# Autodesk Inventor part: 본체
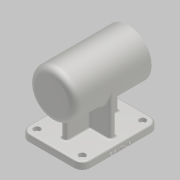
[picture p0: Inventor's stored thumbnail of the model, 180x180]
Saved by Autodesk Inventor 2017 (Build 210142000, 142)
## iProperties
Part Number: 본체
Material: 알루미늄 6061
Document SubType Name: Modeling
Designer: mrc
Density: 2.7 g/cm^3
Appearance: 알루미늄 - 평지
Mass: 1026.28 g
Surface Area: 757.984 cm^2
Volume: 380.103 cm^3
Author: mrc
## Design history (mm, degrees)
sketch "스케치1"
  geometry: L1 (-56, 0)-(56, 0); L2 (-56, 0)-(-56, 34); L3 (-56, 34)-(56, 34); L4 (56, 34)-(56, 21); L5 (56, 21)-(41, 21); L6 (41, 21)-(41, 24); L7 (41, 24)-(-13, 24); L8 (-13, 24)-(-13, 21); L9 (-13, 21)-(-25, 21); L10 (-25, 21)-(-25, 17.5); L11 (-25, 17.5)-(-43, 17.5); L12 (-43, 17.5)-(-43, 16); L13 (-43, 16)-(-47, 16); L14 (-47, 16)-(-47, 10.5); L15 (-47, 10.5)-(-50, 10.5); L16 (-50, 10.5)-(-50, 0); L17 (-50, 0)-(-56, 0); 2 further points
  constraints: 34 end point, 13 perpendicular, 3 point on line, 2 coincident, 2 horizontal, 1 horizontal alignment, 1 midpoint, 1 vertical
  dimensions: "d0" = 112 distance of L1.start L1.end; "d1" = 112 distance between parallel lines of L4 L2; "d2" = 3 distance between parallel lines of L14 L16; "d3" = 4 distance between parallel lines of L12 L14; "d4" = 18 distance between parallel lines of L10 L12; "d5" = 12 distance between parallel lines of L8 L10; "d6" = 54 distance between parallel lines of L6 L8; "d9" = 15 distance of L4.end L5.end; "d10" = 42 diameter of L5 L1; "d11" = 48 diameter of L7 L1; "d12" = 35 diameter of L11 L1; "d13" = 32 diameter of L13 L1; "d14" = 21 diameter of L15 L1; "d15" = 68 diameter of L3 L1
revolve "회전1" sketch "스케치1" stored, may be unused: angle "d16" = 90 deg
sketch "스케치2"
  geometry: 2 further points
  constraints: 1 vertical alignment
  dimensions: "d17" = 26 distance of point (0, 0) point (0, -26)
hole "구멍1" sketch "스케치2" at (0, -26) diameter "d18" = 3.242; stored, may be unused: countersink angle "d22" = 90 deg, drill point angle "d24" = 118 deg; dims "d19" = 8, "d20" = 4, "d21" = 2, "d23" = 11
node "작업 평면1"
sketch "스케치3"
  geometry: L1 (-45, -56)-(45, -56); L2 (45, -56)-(45, 56); L3 (45, 56)-(-45, 56); L4 (-45, 56)-(-45, -56); 3 further points
  constraints: 8 end point, 2 midpoint, 2 parallel, 1 horizontal, 1 horizontal alignment, 1 perpendicular, 1 vertical alignment
  dimensions: "d29" = 112 distance between parallel lines of L3 L1; "d30" = 90 distance between parallel lines of L2 L4
extrude "돌출1" join sketch "스케치3" distance "d31" = 10; taper "d32" = 0 deg
fillet "모깎기1" dims "d33" = 12
sketch "스케치4"
  geometry: A1 r 12 centre (-33, 44) between (-33, 56) and (-45, 44) reference; A2 r 12 centre (-33, -44) between (-45, -44) and (-33, -56) reference; A3 r 12 centre (33, -44) between (33, -56) and (45, -44) reference; A4 r 12 centre (33, 44) between (45, 44) and (33, 56) reference; 5 further points
  constraints: 4 coincident
hole "구멍2" sketch "스케치4" at (-33, 44), (33, 44), (33, -44), (-33, -44) diameter "d34" = 5.5; stored, may be unused: countersink angle "d38" = 90 deg, drill point angle "d40" = 118 deg; dims "d35" = 8, "d36" = 9.5, "d37" = 5.4, "d39" = 11
sketch "스케치5"
  geometry: L1 (-4, -38)-(4, -38); L2 (4, -38)-(4, 38); L3 (4, 38)-(-4, 38); L4 (-4, 38)-(-4, -38); L5 (-34, -4)-(34, -4); L6 (34, -4)-(34, 4); L7 (34, 4)-(-34, 4); L8 (-34, 4)-(-34, -4); 5 further points
  constraints: 16 end point, 4 midpoint, 4 parallel, 2 horizontal, 2 horizontal alignment, 2 perpendicular, 2 vertical alignment
  dimensions: "d41" = 8 distance between parallel lines of L2 L4; "d42" = 76 distance between parallel lines of L1 L3; "d43" = 8 distance between parallel lines of L7 L5; "d44" = 68 distance between parallel lines of L6 L8
extrude "돌출2" join sketch "스케치5" stored distance "d45" = 10; taper "d46" = 0 deg
node "작업 평면2"
sketch "스케치6"
  geometry: L1 (0, 100)-(-10, 100) reference; L2 (0, 100)-(0, 88) reference; 2 further points
  constraints: 1 other
  dimensions: "d48" = 56 distance from line of L1 point (-3, 44); "d49" = 3 distance from line of L2 point (-3, 44)
feature "엠보싱1" sketch "스케치6" dims "d50" = 0.5, "d51" = 0
chamfer "모따기1" distance "d52" = 1; stored, may be unused: second distance "d53" = 2, angle "d54" = 45 deg
fillet "모깎기2" dims "d55" = 10
fillet "모깎기3" dims "d56" = 0.3
fillet "모깎기4" dims "d57" = 3
fillet "모깎기5" dims "d58" = 3
fillet "모깎기6" dims "d59" = 3
fillet "모깎기7" dims "d60" = 3
node "솔리드1"
pattern_circular "원형 패턴1" dims angle "d26" = 360 deg
other parameters: "d28" = -74, "d47" = 5
